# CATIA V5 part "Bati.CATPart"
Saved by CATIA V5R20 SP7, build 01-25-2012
Part number: Bati
Material "Bronze": density 8860 kg/m3, Young's modulus 1.1e+11 Pa, Poisson ratio 0.341, thermal expansion 1.78e-05 1/K
Bounding box of the stored display mesh (mm): x -14 to -2, y -1.832 to 26.773, z -2.721 to 11.896
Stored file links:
  J:\IFMA\IAO\système avant mef\Bati.CATPart
  C:\Appli\Dassault Systemes\B20\intel_a\startup\materials\French\Catalog.CATMaterial
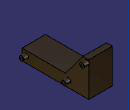
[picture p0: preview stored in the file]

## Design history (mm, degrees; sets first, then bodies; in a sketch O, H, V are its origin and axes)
Body1 (main body), material "Bronze"
  Plane1: stored without definition
  Plane2: stored without definition
  Sketch1 on Plane1, origin (-4, 0, 0), H (0, 1, 0), V (0, 0, 1)
    line L1 (-1.8324, -2.7209) -> (26.6164, -2.7209)
    line L2 (26.6164, -2.7209) -> (26.6164, 11.896)
    line L3 (26.6164, 11.896) -> (24.1198, 11.896)
    line L4 (24.1198, 11.896) -> (16.6608, 1.9664)
    line L5 (16.6608, 1.9664) -> (-1.8324, 1.9664)
    line L6 (-1.8324, 1.9664) -> (-1.8324, -2.7209)
    horizontal: L1 H, L3 H, L5 H
    vertical: L2 V, L6 V
  Pad1: profile Sketch1, direction (-1, 0, 0), length 10
  Point1 "Point.F": stored without definition
  Sketch2 on start face of Pad1, origin (-4, 0, 0), H (0, 1, 0), V (0, 0, 1)
    circle A1 centre (0, 0) radius 1
    point P1 (0, 0)
    reference projected point E1 (0, 0) from Point1
    radius A1 = 1
    coincidence: P1 E1
  Pad2: profile Sketch2, direction (1, 0, 0), length 2
  Point2 "Point.C": stored without definition
  Sketch3 on start face of Pad1, origin (-4, 0, 0), H (0, 1, 0), V (0, 0, 1)
    circle A1 centre (18, 0) radius 1
    point P1 (18, 0)
    reference projected point E1 (18, 0) from Point2
    radius A1 = 1
    coincidence: P1 E1
  Pad3: profile Sketch3, direction (1, 0, 0), length 2
  Point3 "Point.E": stored without definition
  Sketch4 on start face of Pad1, origin (-4, 0, 0), H (0, 1, 0), V (0, 0, 1)
    circle A1 centre (25.7733, 10.4199) radius 1
    point P1 (25.7733, 10.4199)
    reference projected point E1 (25.7733, 10.4199) from Point3
    radius A1 = 1
    coincidence: P1 E1
  Pad4: profile Sketch4, direction (1, 0, 0), length 2
  Sketch5 on end face of Pad4, origin (-2, 25.7733, 10.4199), H (0, 1, 0), V (0, 0, 1)
    point P1 (0, 0)
  Hole1: placed by Sketch5, at (-2, 25.7733, 10.4199) direction (-1, 0, 0), diameter 1, depth 7
  Sketch6 on end face of Pad3, origin (-2, 18, 0), H (0, 1, 0), V (0, 0, 1)
    point P1 (0, 0)
  Hole2: placed by Sketch6, at (-2, 18, 0) direction (-1, 0, 0), diameter 1, depth 7
  Sketch7 on end face of Pad2, origin (-2, 0, 0), H (0, 1, 0), V (0, 0, 1)
    point P1 (0, 0)
  Hole3: placed by Sketch7, at (-2, 0, 0) direction (-1, 0, 0), diameter 1, depth 7
  Point4 "Point.F": stored without definition
  Point5 "Point.C": stored without definition
  Point6 "Point.E": stored without definition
